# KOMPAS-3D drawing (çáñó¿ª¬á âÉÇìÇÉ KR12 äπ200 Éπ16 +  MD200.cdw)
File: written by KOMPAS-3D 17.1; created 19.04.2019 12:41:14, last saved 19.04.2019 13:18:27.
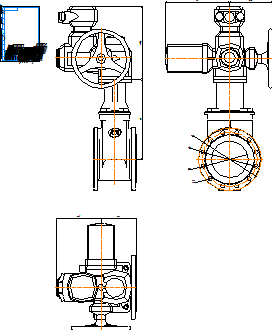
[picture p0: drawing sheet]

Sheet 1: A4, portrait

Title block, sheet 1: name: Задвижка ГРАНАР KR12 Ду200 Ру16 + / MD200; material: Внимание! Данный продукт является объектом авторского права ООО «Торговый Дом АДЛ». / Запрещается изменение, копирование, распространение / (в том числе путем копирования на другие сайты и ресурсы в Интернете) / или любое иное использование информации и объектов без предварительного / согласия правообладателя (ООО «Торговый Дом АДЛ»).; mass: 250,59; sheets: 1; organisation: ООО "Торговый дом АДЛ"; sheet format: A4; stored path: \\adlc.lan\data\АДЛ_ПКД\3D-модели\ADL production\Клиновые задвижки серии KR ГРАНАР\Клиновые задвижки KR12 с эл.приводами Смартгир\KOMPAS 2D\Задвижка ГРАНАР KR12 Ду200 Ру16 +  MD200.cdw

Views: Вид 1, Проекционный вид 3
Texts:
  user
Dimensions and other numbers on the sheet: 430; 391; 241,19; 188,81; 1:1; 1; 250,59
